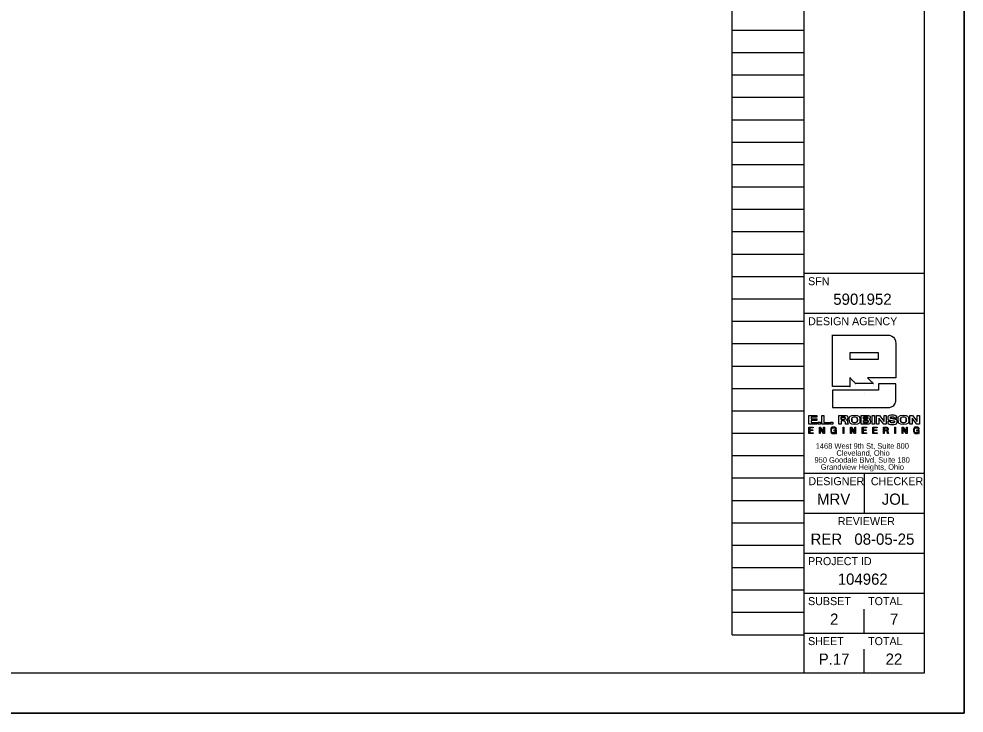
# Model space of a CAD drawing. Extents: x 0 to 44.4, y -4.7 to 22.
# Drawn here: x 22.19 to 34, y 0 to 8.68 of the extents above; entities that cross this region are included whole.
import ezdxf

# ---------------------------------------------------------------- set-up
doc = ezdxf.new("R2010")
doc.units = 0
for name, color, linetype in [('SC_Scratch1', 7, 'Continuous'), ('SH_Border', 7, 'Continuous'), ('SH_Cut_Line', 7, 'Continuous'), ('SH_Data', 7, 'Continuous')]:
    doc.layers.add(name, color=color, linetype=linetype)

msp = doc.modelspace()

# ---------------------------------------------------------------- linework, layer by layer
at = {"layer": 'SC_Scratch1'}
for p, q in [((31.1, 0.98), (31.1, 21.14)), ((32, 0.98), (32, 21.14)), ((31.1, 8.54), (32, 8.54)), ((31.1, 8.26), (32, 8.26)), ((31.1, 7.98), (32, 7.98)), ((31.1, 7.7), (32, 7.7)), ((31.1, 7.42), (32, 7.42)), ((31.1, 7.14), (32, 7.14)), ((31.1, 6.86), (32, 6.86)), ((31.1, 6.58), (32, 6.58)), ((31.1, 6.3), (32, 6.3)), ((31.1, 6.02), (32, 6.02)), ((31.1, 5.74), (32, 5.74)), ((31.1, 5.46), (32, 5.46)), ((31.1, 5.18), (32, 5.18)), ((31.1, 4.9), (32, 4.9)), ((31.1, 4.62), (32, 4.62)), ((31.1, 4.34), (32, 4.34)), ((31.1, 4.06), (32, 4.06)), ((31.1, 3.78), (32, 3.78)), ((31.1, 3.5), (32, 3.5)), ((31.1, 3.22), (32, 3.22)), ((31.1, 2.94), (32, 2.94)), ((31.1, 2.66), (32, 2.66)), ((31.1, 2.38), (32, 2.38)), ((31.1, 2.1), (32, 2.1)), ((31.1, 1.82), (32, 1.82)), ((31.1, 1.54), (32, 1.54)), ((31.1, 1.26), (32, 1.26)), ((31.1, 0.98), (32, 0.98))]:
    msp.add_line(p, q, dxfattribs=at)
msp.add_lwpolyline([(0, 22), (34, 22), (34, 0), (0, 0)], close=True, dxfattribs=at)
at = {"layer": 'SH_Border'}
for p, q in [((32, 0.5), (32, 21.5)), ((32, 5.5), (33.5, 5.5)), ((32, 5), (33.5, 5)), ((32, 3), (33.5, 3)), ((32.75, 3), (32.75, 2.5)), ((32, 2.5), (33.5, 2.5)), ((32, 2), (33.5, 2)), ((32, 1.5), (33.5, 1.5)), ((32, 1), (33.5, 1))]:
    msp.add_line(p, q, dxfattribs=at)
msp.add_lwpolyline([(1.5, 21.5), (33.5, 21.5), (33.5, 0.5), (1.5, 0.5)], close=True, dxfattribs=at)
at = {"layer": 'SH_Cut_Line'}
msp.add_lwpolyline([(0, 0), (34, 0), (34, 22), (0, 22)], close=True, dxfattribs=at)
at = {"layer": 'SH_Data'}
for p, q in [((32.929, 4.503), (32.574, 4.503)), ((32.574, 4.503), (32.574, 4.425)), ((32.929, 4.425), (32.929, 4.503)), ((32.574, 4.425), (32.929, 4.425)), ((32.75, 4), (32.75, 4)), ((32.463, 3.701), (32.463, 3.673)), ((32.743, 3.702), (32.743, 3.678)), ((32.743, 3.659), (32.743, 3.633)), ((33.001, 3.566), (33.001, 3.539)), ((33.001, 3.539), (33.023, 3.539)), ((32.75, 1), (32.75, 1.3)), ((32.75, 0.5), (32.75, 0.8)), ((32.375, 0.675), (32.375, 0.675))]:
    msp.add_line(p, q, dxfattribs=at)
for points in [[(32.06, 3.721), (32.161, 3.721), (32.161, 3.701), (32.089, 3.701), (32.089, 3.678), (32.158, 3.678), (32.158, 3.658), (32.089, 3.658), (32.089, 3.633), (32.162, 3.633), (32.162, 3.613), (32.06, 3.613), (32.06, 3.721)], [(32.22, 3.721), (32.249, 3.721), (32.249, 3.634), (32.316, 3.634), (32.316, 3.613), (32.22, 3.613), (32.22, 3.721)], [(32.851, 3.721), (32.881, 3.721), (32.881, 3.613), (32.851, 3.613), (32.851, 3.721)], [(32.999, 3.721), (33.027, 3.721), (33.027, 3.613), (32.995, 3.613), (32.936, 3.689), (32.936, 3.689), (32.936, 3.613), (32.907, 3.613), (32.907, 3.721), (32.941, 3.721), (32.999, 3.646), (32.999, 3.646), (32.999, 3.721)], [(33.413, 3.721), (33.442, 3.721), (33.442, 3.613), (33.41, 3.613), (33.35, 3.689), (33.35, 3.689), (33.35, 3.613), (33.321, 3.613), (33.321, 3.721), (33.356, 3.721), (33.413, 3.646), (33.413, 3.646), (33.413, 3.721)], [(32.059, 3.575), (32.114, 3.575), (32.114, 3.566), (32.07, 3.566), (32.07, 3.541), (32.111, 3.541), (32.111, 3.532), (32.07, 3.532), (32.07, 3.505), (32.114, 3.505), (32.114, 3.496), (32.059, 3.496), (32.059, 3.575)], [(32.175, 3.639), (32.205, 3.639), (32.205, 3.613), (32.175, 3.613), (32.175, 3.639)], [(32.191, 3.575), (32.203, 3.575), (32.244, 3.511), (32.244, 3.511), (32.244, 3.575), (32.254, 3.575), (32.254, 3.496), (32.243, 3.496), (32.202, 3.559), (32.201, 3.559), (32.201, 3.496), (32.191, 3.496), (32.191, 3.575)], [(32.331, 3.639), (32.361, 3.639), (32.361, 3.613), (32.331, 3.613), (32.331, 3.639)], [(32.487, 3.575), (32.498, 3.575), (32.498, 3.496), (32.487, 3.496), (32.487, 3.575)], [(32.581, 3.575), (32.592, 3.575), (32.633, 3.511), (32.633, 3.511), (32.633, 3.575), (32.643, 3.575), (32.643, 3.496), (32.632, 3.496), (32.591, 3.559), (32.591, 3.559), (32.591, 3.496), (32.581, 3.496), (32.581, 3.575)], [(32.726, 3.575), (32.781, 3.575), (32.781, 3.566), (32.737, 3.566), (32.737, 3.541), (32.778, 3.541), (32.778, 3.532), (32.737, 3.532), (32.737, 3.505), (32.781, 3.505), (32.781, 3.496), (32.726, 3.496), (32.726, 3.575)], [(32.859, 3.575), (32.913, 3.575), (32.913, 3.566), (32.869, 3.566), (32.869, 3.541), (32.91, 3.541), (32.91, 3.532), (32.869, 3.532), (32.869, 3.505), (32.913, 3.505), (32.913, 3.496), (32.859, 3.496), (32.859, 3.575)], [(33.133, 3.575), (33.143, 3.575), (33.143, 3.496), (33.133, 3.496), (33.133, 3.575)], [(33.226, 3.575), (33.237, 3.575), (33.279, 3.511), (33.279, 3.511), (33.279, 3.575), (33.289, 3.575), (33.289, 3.496), (33.277, 3.496), (33.236, 3.559), (33.236, 3.559), (33.236, 3.496), (33.226, 3.496), (33.226, 3.575)]]:
    msp.add_lwpolyline(points, dxfattribs=at)
for points, degree in [([(32.356, 4.083), (32.356, 4.086), (32.356, 4.724), (32.356, 4.727)], 2), ([(32.356, 4.727), (32.36, 4.727), (33.03, 4.727), (33.034, 4.727), (33.096, 4.727), (33.147, 4.677), (33.147, 4.614)], 3), ([(33.147, 4.614), (33.147, 4.612), (33.147, 4.194), (33.147, 4.192)], 2), ([(32.645, 4.121), (32.645, 4.121), (32.574, 4.191), (32.574, 4.192)], 2), ([(32.574, 4.192), (32.574, 4.191), (32.574, 4.083), (32.574, 4.083)], 2), ([(33.147, 4.192), (33.145, 4.192), (32.795, 4.192), (32.793, 4.192)], 2), ([(32.793, 4.192), (32.793, 4.191), (32.866, 4.121), (32.866, 4.121)], 2), ([(32.929, 4.115), (32.929, 4.115), (33.147, 4.115), (33.147, 4.115), (33.147, 4.115), (33.147, 3.933), (33.147, 3.933), (33.147, 3.87), (33.096, 3.82), (33.034, 3.82), (33.034, 3.82), (32.356, 3.82), (32.356, 3.82), (32.356, 3.82), (32.356, 4.037), (32.356, 4.037), (32.356, 4.037), (32.929, 4.037), (32.929, 4.037), (32.929, 4.037), (32.929, 4.115), (32.929, 4.115)], 3), ([(32.574, 4.083), (32.573, 4.083), (32.357, 4.083), (32.356, 4.083)], 2), ([(32.866, 4.121), (32.865, 4.121), (32.646, 4.121), (32.645, 4.121)], 2), ([(32.433, 3.613), (32.433, 3.613), (32.433, 3.721), (32.433, 3.721)], 2), ([(32.433, 3.721), (32.433, 3.721), (32.512, 3.721), (32.512, 3.721), (32.542, 3.721), (32.545, 3.703), (32.546, 3.692)], 3), ([(32.463, 3.673), (32.463, 3.673), (32.502, 3.673), (32.502, 3.673), (32.508, 3.673), (32.516, 3.677), (32.516, 3.687), (32.516, 3.698), (32.507, 3.701), (32.5, 3.701), (32.5, 3.701), (32.463, 3.701), (32.463, 3.701), (32.463, 3.701), (32.463, 3.673), (32.463, 3.673)], 3), ([(32.463, 3.673), (32.476, 3.673), (32.489, 3.673), (32.508, 3.673), (32.516, 3.677), (32.516, 3.698), (32.507, 3.701), (32.488, 3.701), (32.475, 3.701), (32.463, 3.701)], 3), ([(32.546, 3.692), (32.544, 3.679), (32.542, 3.67), (32.53, 3.666)], 2), ([(32.53, 3.666), (32.53, 3.666), (32.53, 3.665), (32.53, 3.665)], 2), ([(32.53, 3.665), (32.543, 3.663), (32.544, 3.647), (32.544, 3.636)], 2), ([(32.631, 3.61), (32.573, 3.61), (32.567, 3.645), (32.565, 3.667), (32.564, 3.69), (32.573, 3.724), (32.631, 3.724)], 3), ([(32.631, 3.63), (32.658, 3.63), (32.667, 3.65), (32.667, 3.667), (32.667, 3.684), (32.658, 3.704), (32.631, 3.704), (32.604, 3.704), (32.595, 3.684), (32.595, 3.667), (32.595, 3.65), (32.604, 3.63), (32.631, 3.63)], 3), ([(32.631, 3.704), (32.604, 3.704), (32.595, 3.684), (32.595, 3.667), (32.595, 3.65), (32.604, 3.63), (32.631, 3.63)], 3), ([(32.631, 3.724), (32.69, 3.724), (32.695, 3.689), (32.697, 3.667), (32.699, 3.644), (32.69, 3.61), (32.631, 3.61)], 3), ([(32.631, 3.63), (32.658, 3.63), (32.667, 3.65), (32.667, 3.667), (32.667, 3.684), (32.658, 3.704), (32.631, 3.704)], 3), ([(32.714, 3.613), (32.714, 3.613), (32.714, 3.721), (32.714, 3.721)], 2), ([(32.714, 3.721), (32.714, 3.721), (32.795, 3.721), (32.795, 3.721)], 2), ([(32.743, 3.678), (32.743, 3.678), (32.784, 3.678), (32.784, 3.678), (32.791, 3.678), (32.796, 3.682), (32.796, 3.69), (32.796, 3.697), (32.793, 3.702), (32.78, 3.702), (32.78, 3.702), (32.743, 3.702), (32.743, 3.702), (32.743, 3.702), (32.743, 3.678), (32.743, 3.678)], 3), ([(32.743, 3.678), (32.757, 3.678), (32.771, 3.678), (32.791, 3.681), (32.791, 3.683), (32.792, 3.697), (32.793, 3.702), (32.768, 3.702), (32.756, 3.702), (32.743, 3.702)], 3), ([(32.795, 3.721), (32.81, 3.718), (32.826, 3.714), (32.826, 3.694)], 2), ([(32.826, 3.694), (32.824, 3.686), (32.822, 3.675), (32.812, 3.672)], 2), ([(32.812, 3.672), (32.812, 3.672), (32.812, 3.672), (32.812, 3.672)], 2), ([(32.812, 3.672), (32.824, 3.67), (32.827, 3.656), (32.829, 3.645)], 2), ([(33.126, 3.69), (33.124, 3.704), (33.111, 3.706), (33.099, 3.706), (33.087, 3.706), (33.079, 3.7), (33.079, 3.693), (33.079, 3.687), (33.084, 3.684), (33.091, 3.683), (33.091, 3.683), (33.128, 3.677), (33.128, 3.677), (33.148, 3.673), (33.163, 3.666), (33.163, 3.646), (33.163, 3.626), (33.149, 3.61), (33.107, 3.61), (33.08, 3.61), (33.046, 3.613), (33.045, 3.647), (33.045, 3.647), (33.079, 3.647), (33.079, 3.647), (33.079, 3.632), (33.094, 3.629), (33.107, 3.629), (33.121, 3.629), (33.13, 3.634), (33.13, 3.643), (33.13, 3.651), (33.123, 3.654), (33.112, 3.655), (33.112, 3.655), (33.085, 3.66), (33.085, 3.66), (33.066, 3.662), (33.047, 3.668), (33.047, 3.69), (33.047, 3.715), (33.067, 3.724), (33.101, 3.724), (33.124, 3.724), (33.157, 3.721), (33.159, 3.69), (33.159, 3.69), (33.126, 3.69), (33.126, 3.69)], 3), ([(33.242, 3.61), (33.183, 3.61), (33.178, 3.645), (33.176, 3.667), (33.174, 3.69), (33.183, 3.724), (33.242, 3.724)], 3), ([(33.242, 3.63), (33.269, 3.63), (33.278, 3.65), (33.278, 3.667), (33.278, 3.684), (33.269, 3.704), (33.242, 3.704), (33.215, 3.704), (33.205, 3.684), (33.205, 3.667), (33.205, 3.65), (33.215, 3.63), (33.242, 3.63)], 3), ([(33.242, 3.704), (33.215, 3.704), (33.205, 3.684), (33.205, 3.667), (33.205, 3.65), (33.215, 3.63), (33.242, 3.63)], 3), ([(33.242, 3.724), (33.3, 3.724), (33.306, 3.689), (33.308, 3.667), (33.309, 3.644), (33.3, 3.61), (33.242, 3.61)], 3), ([(33.242, 3.63), (33.269, 3.63), (33.278, 3.65), (33.278, 3.667), (33.278, 3.684), (33.269, 3.704), (33.242, 3.704)], 3), ([(32.396, 3.506), (32.39, 3.498), (32.38, 3.494), (32.37, 3.494), (32.347, 3.494), (32.333, 3.514), (32.333, 3.534), (32.333, 3.557), (32.346, 3.577), (32.37, 3.577), (32.388, 3.577), (32.401, 3.569), (32.404, 3.551), (32.404, 3.551), (32.394, 3.551), (32.394, 3.551), (32.392, 3.562), (32.382, 3.568), (32.37, 3.568), (32.351, 3.568), (32.344, 3.551), (32.344, 3.534), (32.344, 3.518), (32.353, 3.503), (32.37, 3.503), (32.387, 3.503), (32.396, 3.515), (32.396, 3.529), (32.396, 3.529), (32.371, 3.529), (32.371, 3.529), (32.371, 3.529), (32.371, 3.538), (32.371, 3.538), (32.371, 3.538), (32.405, 3.538), (32.405, 3.538), (32.405, 3.538), (32.405, 3.496), (32.405, 3.496), (32.405, 3.496), (32.398, 3.496), (32.398, 3.496), (32.398, 3.496), (32.396, 3.506), (32.396, 3.506)], 3), ([(32.463, 3.613), (32.462, 3.613), (32.433, 3.613), (32.433, 3.613)], 2), ([(32.499, 3.653), (32.499, 3.653), (32.463, 3.653), (32.463, 3.653)], 2), ([(32.463, 3.653), (32.463, 3.652), (32.463, 3.613), (32.463, 3.613)], 2), ([(32.518, 3.613), (32.516, 3.618), (32.516, 3.622), (32.516, 3.634), (32.515, 3.649), (32.508, 3.65), (32.499, 3.653)], 3), ([(32.55, 3.613), (32.55, 3.613), (32.518, 3.613), (32.518, 3.613)], 2), ([(32.544, 3.636), (32.544, 3.631), (32.548, 3.619), (32.55, 3.613)], 2), ([(32.829, 3.645), (32.827, 3.632), (32.824, 3.613), (32.791, 3.613), (32.791, 3.613), (32.714, 3.613), (32.714, 3.613)], 3), ([(32.743, 3.633), (32.743, 3.633), (32.787, 3.633), (32.787, 3.633), (32.796, 3.633), (32.8, 3.639), (32.8, 3.646), (32.8, 3.655), (32.794, 3.659), (32.784, 3.659), (32.784, 3.659), (32.743, 3.659), (32.743, 3.659), (32.743, 3.659), (32.743, 3.633), (32.743, 3.633)], 3), ([(32.743, 3.633), (32.758, 3.633), (32.772, 3.633), (32.796, 3.633), (32.8, 3.639), (32.8, 3.655), (32.794, 3.659), (32.77, 3.659), (32.757, 3.659), (32.743, 3.659)], 3), ([(32.991, 3.575), (32.991, 3.575), (33.027, 3.575), (33.028, 3.575), (33.042, 3.575), (33.051, 3.567), (33.051, 3.554)], 3), ([(32.991, 3.496), (32.991, 3.497), (32.991, 3.574), (32.991, 3.575)], 2), ([(33.023, 3.539), (33.033, 3.539), (33.041, 3.541), (33.041, 3.552), (33.041, 3.56), (33.037, 3.566), (33.027, 3.566), (33.027, 3.566), (33.001, 3.566), (33.001, 3.566), (33.001, 3.566), (33.001, 3.539), (33.001, 3.539), (33.001, 3.539), (33.023, 3.539), (33.023, 3.539)], 3), ([(33.023, 3.539), (33.033, 3.539), (33.041, 3.541), (33.041, 3.56), (33.037, 3.566), (33.018, 3.566), (33.01, 3.566), (33.001, 3.566)], 3), ([(33.051, 3.554), (33.049, 3.545), (33.047, 3.537), (33.038, 3.534)], 2), ([(33.43, 3.506), (33.424, 3.498), (33.414, 3.494), (33.405, 3.494), (33.382, 3.494), (33.368, 3.514), (33.368, 3.534), (33.368, 3.557), (33.38, 3.577), (33.405, 3.577), (33.422, 3.577), (33.436, 3.569), (33.439, 3.551), (33.439, 3.551), (33.429, 3.551), (33.429, 3.551), (33.426, 3.562), (33.417, 3.568), (33.405, 3.568), (33.386, 3.568), (33.378, 3.551), (33.378, 3.534), (33.378, 3.518), (33.388, 3.503), (33.405, 3.503), (33.421, 3.503), (33.431, 3.515), (33.43, 3.529), (33.43, 3.529), (33.405, 3.529), (33.405, 3.529), (33.405, 3.529), (33.405, 3.538), (33.405, 3.538), (33.405, 3.538), (33.44, 3.538), (33.44, 3.538), (33.44, 3.538), (33.44, 3.496), (33.44, 3.496), (33.44, 3.496), (33.433, 3.496), (33.433, 3.496), (33.433, 3.496), (33.43, 3.506), (33.43, 3.506)], 3), ([(33.001, 3.496), (33.001, 3.496), (32.991, 3.496), (32.991, 3.496)], 2), ([(33.04, 3.516), (33.038, 3.523), (33.037, 3.53), (33.027, 3.53), (33.027, 3.53), (33.001, 3.53), (33.001, 3.53)], 3), ([(33.001, 3.53), (33.001, 3.53), (33.001, 3.496), (33.001, 3.496)], 2), ([(33.038, 3.534), (33.038, 3.534), (33.038, 3.534), (33.038, 3.534)], 2), ([(33.038, 3.534), (33.044, 3.529), (33.047, 3.525), (33.048, 3.518)], 2), ([(33.043, 3.496), (33.042, 3.5), (33.041, 3.508), (33.04, 3.516)], 2), ([(33.054, 3.496), (33.054, 3.496), (33.043, 3.496), (33.043, 3.496)], 2), ([(33.048, 3.518), (33.049, 3.51), (33.052, 3.502), (33.054, 3.496)], 2)]:
    msp.add_open_spline(points, degree=degree, dxfattribs=at)

# ---------------------------------------------------------------- texts
for s, height, p in [('SFN', 0.1, (32.05, 5.35)), ('5901952', 0.14, (32.365, 5.105)), ('DESIGN AGENCY', 0.1, (32.05, 4.85)), ('1468 West 9th St, Suite 800', 0.07, (32.145, 3.305)), ('950 Goodale Blvd, Suite 180', 0.07, (32.13, 3.13)), ('Cleveland, Ohio', 0.07, (32.404, 3.217)), ('Grandview Heights, Ohio', 0.07, (32.208, 3.042)), ('DESIGNER', 0.1, (32.054, 2.85)), ('CHECKER', 0.1, (32.835, 2.85)), ('MRV', 0.14, (32.162, 2.605)), ('JOL', 0.14, (32.971, 2.605)), ('REVIEWER', 0.1, (32.422, 2.35)), ('RER', 0.14, (32.081, 2.105)), ('08-05-25', 0.14, (32.629, 2.105)), ('PROJECT ID', 0.1, (32.05, 1.85)), ('104962', 0.14, (32.421, 1.605)), ('SUBSET', 0.1, (32.05, 1.35)), ('TOTAL', 0.1, (32.8, 1.35)), ('2', 0.14, (32.325, 1.105)), ('7', 0.14, (33.074, 1.105)), ('SHEET', 0.1, (32.05, 0.85)), ('TOTAL', 0.1, (32.8, 0.85)), ('P.17', 0.14, (32.183, 0.605)), ('22', 0.14, (33.019, 0.605))]:
    msp.add_text(s, height=height, dxfattribs=at).set_placement(p)

doc.saveas('drawing.dxf')
